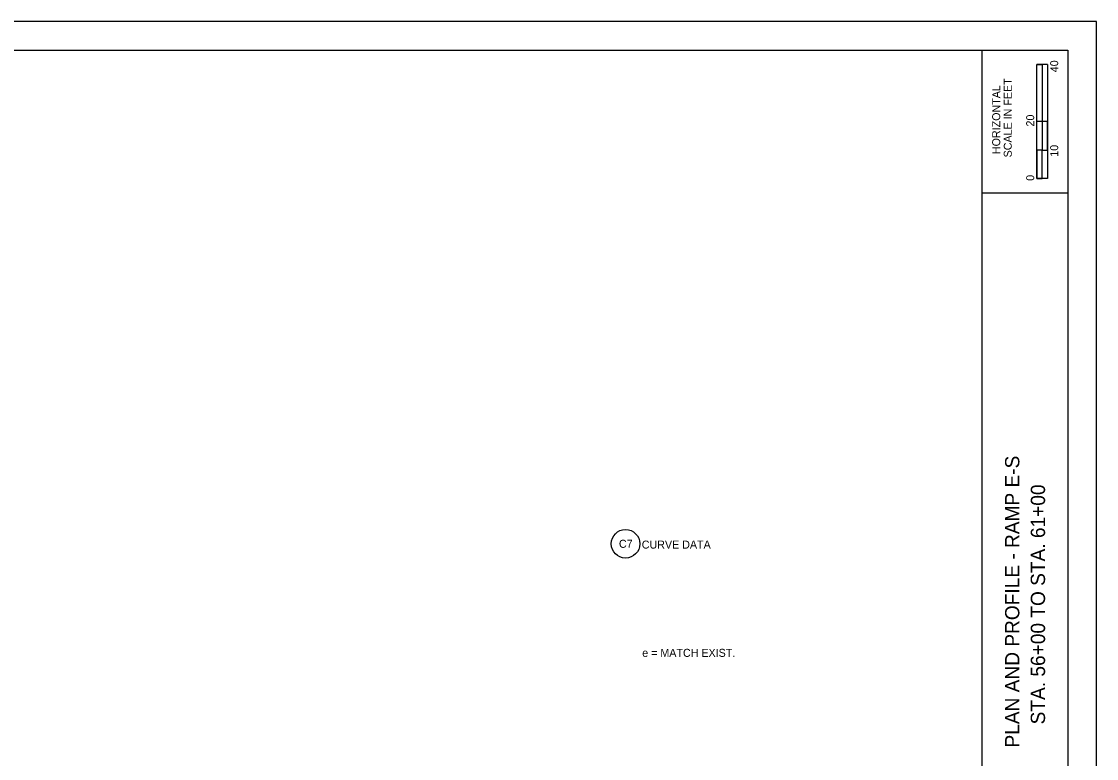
# Model space of a CAD drawing. Extents: x -3.6 to 34, y 0 to 22.
# Drawn here: x 15.19 to 34, y 9.1 to 22 of the extents above; entities that cross this region are included whole.
import ezdxf

# ---------------------------------------------------------------- set-up
doc = ezdxf.new("R2010")
doc.units = 0
for name, color, linetype in [('Default', 7, 'Continuous'), ('SH_Border', 7, 'Continuous'), ('SH_Cut_Line', 7, 'Continuous'), ('SH_Data', 7, 'Continuous')]:
    doc.layers.add(name, color=color, linetype=linetype)

msp = doc.modelspace()

# ---------------------------------------------------------------- linework, layer by layer
at = {"layer": 'Default'}
msp.add_circle((25.759, 12.858), 0.25, dxfattribs=at)
at = {"layer": 'SH_Border'}
for p, q in [((32, 0.5), (32, 21.5)), ((32, 19), (33.5, 19))]:
    msp.add_line(p, q, dxfattribs=at)
msp.add_lwpolyline([(1.5, 21.5), (33.5, 21.5), (33.5, 0.5), (1.5, 0.5)], close=True, dxfattribs=at)
at = {"layer": 'SH_Cut_Line'}
msp.add_lwpolyline([(0, 0), (34, 0), (34, 22), (0, 22)], close=True, dxfattribs=at)
at = {"layer": 'SH_Data'}
for p, q in [((32.957, 19.25), (32.957, 21.25)), ((33.144, 21.25), (32.957, 21.25)), ((32.957, 20.25), (32.957, 21.25)), ((32.957, 21.25), (33.05, 21.25)), ((33.05, 21.25), (33.051, 21.25)), ((33.051, 21.25), (33.051, 20.25)), ((33.144, 21.25), (33.144, 19.25)), ((33.051, 20.25), (32.957, 20.25)), ((33.143, 20.25), (33.05, 20.25)), ((33.05, 20.25), (33.05, 19.75)), ((33.143, 19.75), (33.143, 20.25)), ((33.05, 19.75), (32.957, 19.75)), ((32.957, 19.75), (32.957, 19.25)), ((33.05, 19.25), (33.05, 19.75)), ((33.05, 19.75), (33.143, 19.75)), ((33.144, 19.25), (32.957, 19.25)), ((32.957, 19.25), (33.05, 19.25))]:
    msp.add_line(p, q, dxfattribs=at)

# ---------------------------------------------------------------- texts
at = {"layer": 'Default'}
for s, p in [('C7', (25.643, 12.788)), ('CURVE DATA', (26.043, 12.774)), ('e = MATCH EXIST. ', (26.051, 10.879))]:
    msp.add_text(s, height=0.14, dxfattribs=at).set_placement(p)
at = {"layer": 'SH_Data'}
for s, height, p in [('40', 0.14, (33.33, 21.112)), ('SCALE IN FEET', 0.14, (32.517, 19.621)), ('HORIZONTAL', 0.14, (32.315, 19.679)), ('20', 0.14, (32.91, 20.162)), ('10', 0.14, (33.33, 19.633)), ('0', 0.14, (32.91, 19.211)), ('PLAN AND PROFILE - RAMP E-S', 0.25, (32.65, 9.292)), ('STA. 56+00 TO STA. 61+00', 0.25, (33.1, 9.697))]:
    msp.add_text(s, height=height, rotation=90, dxfattribs=at).set_placement(p)

doc.saveas('drawing.dxf')
